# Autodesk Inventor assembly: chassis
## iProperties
Shininess: 64.0
Length Units: 11269
Angle Units: 11279
Time Units: 11290
Mass Units: 11283
Length Display Precision: 3
Angle Display Precision: 2
Compacted: True
Created: 2005-04
Part Number: chassis
Document SubType Name: Assembly
Designer: thchene
Density: 0.0
Volumn: 0.0
Area: 0.0
PropertySet Name: Model Information
Control State: 0
Master: False
Checked Out: False
Author: thchene
